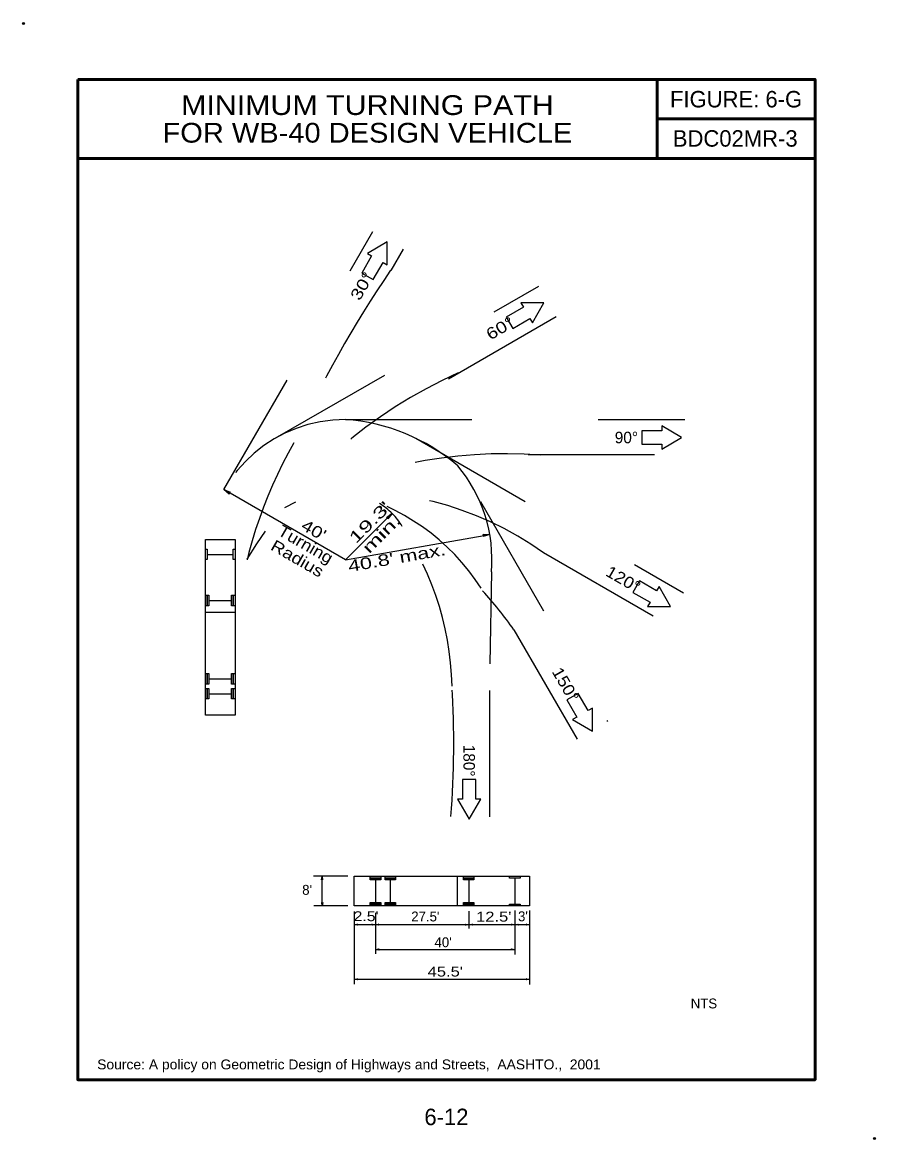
# Model space of a CAD drawing. Extents: x -4.063 to -3.388, y 4.885 to 5.77.
import ezdxf
from ezdxf.enums import TextEntityAlignment as Align

# ---------------------------------------------------------------- set-up
doc = ezdxf.new("R2010")
doc.units = 0
doc.header["$LTSCALE"] = 0.0036
doc.header["$PDMODE"] = 32
doc.header["$PDSIZE"] = 0.0018
doc.linetypes.add('LONG_DASHED', pattern=[7.5, 6, -1.5])
doc.layers.add('1', color=7, linetype='Continuous', lineweight=25)
doc.layers.add('2', color=7, linetype='Continuous', lineweight=25)

msp = doc.modelspace()

# ---------------------------------------------------------------- linework, layer by layer
at = {"layer": '1', "lineweight": 53}
for p, q in [((-3.561125, 5.724317), (-3.561125, 5.661817)), ((-3.561125, 5.693067), (-3.436125, 5.693067)), ((-4.019458, 5.661817), (-3.436125, 5.661817))]:
    msp.add_line(p, q, dxfattribs=at)
at = {"layer": '1', "linetype": 'LONG_DASHED'}
for p, q in [((-3.903883, 5.399658), (-3.785933, 5.60395)), ((-3.771617, 5.573192), (-3.761875, 5.590058)), ((-3.863217, 5.440342), (-3.6548, 5.560675)), ((-3.726175, 5.487367), (-3.640908, 5.536608)), ((-3.807658, 5.455225), (-3.539267, 5.455225)), ((-3.7521, 5.440342), (-3.540125, 5.317967)), ((-3.663042, 5.427442), (-3.539267, 5.427442)), ((-3.700908, 5.390267), (-3.600367, 5.21615)), ((-3.650883, 5.349825), (-3.554008, 5.2939)), ((-3.692167, 5.334567), (-3.693392, 5.261683)), ((-3.674375, 5.288775), (-3.624417, 5.202258))]:
    msp.add_line(p, q, dxfattribs=at)
at = {"layer": '1'}
for p, q in [((-3.903908, 5.399692), (-3.898892, 5.397642)), ((-3.7708, 5.380908), (-3.774058, 5.376592)), ((-3.693458, 5.364233), (-3.6986, 5.362567)), ((-3.917058, 5.348425), (-3.896417, 5.348425)), ((-3.915667, 5.311967), (-3.897808, 5.311967)), ((-3.918458, 5.302733), (-3.895017, 5.302733)), ((-3.915667, 5.2499), (-3.897808, 5.2499)), ((-3.915667, 5.238183), (-3.897808, 5.238183)), ((-3.805925, 5.09365), (-3.833008, 5.09365)), ((-3.826075, 5.070217), (-3.826075, 5.093717)), ((-3.719392, 5.09365), (-3.719392, 5.070217)), ((-3.826133, 5.093533), (-3.825742, 5.090858)), ((-3.78395, 5.090858), (-3.78395, 5.073008)), ((-3.772225, 5.090858), (-3.772225, 5.073008)), ((-3.710167, 5.090858), (-3.710167, 5.073008)), ((-3.673708, 5.092258), (-3.673708, 5.071608)), ((-3.8057, 5.070217), (-3.832792, 5.070217)), ((-3.826092, 5.070283), (-3.826492, 5.072967)), ((-3.800875, 5.065825), (-3.800875, 5.0083)), ((-3.783925, 5.0647), (-3.783925, 5.032267)), ((-3.709992, 5.06605), (-3.709992, 5.052308)), ((-3.673617, 5.066492), (-3.673617, 5.031817)), ((-3.661992, 5.066608), (-3.661992, 5.007983)), ((-3.800875, 5.055408), (-3.661917, 5.055408)), ((-3.800833, 5.055383), (-3.798158, 5.055775)), ((-3.78395, 5.055383), (-3.786625, 5.054983)), ((-3.783942, 5.055408), (-3.781258, 5.0558)), ((-3.710017, 5.05535), (-3.7127, 5.05495)), ((-3.70995, 5.055425), (-3.707267, 5.055817)), ((-3.673617, 5.055408), (-3.676292, 5.055017)), ((-3.6736, 5.055433), (-3.670925, 5.055825)), ((-3.662, 5.055408), (-3.664675, 5.055017)), ((-3.783867, 5.0357), (-3.673783, 5.0357)), ((-3.78385, 5.035733), (-3.781175, 5.036133)), ((-3.673683, 5.035717), (-3.676367, 5.035317)), ((-3.800875, 5.012108), (-3.662042, 5.012108)), ((-3.8008, 5.012117), (-3.798125, 5.012517)), ((-3.662017, 5.012108), (-3.6647, 5.011717))]:
    msp.add_line(p, q, dxfattribs=at)
at = {"layer": '1', "lineweight": 53}
msp.add_lwpolyline([(-4.019458, 5.724317), (-3.436125, 5.724317), (-3.436125, 4.93265), (-4.019458, 4.93265)], close=True, dxfattribs=at)
at = {"layer": '1'}
for points in [[(-3.794767, 5.571117), (-3.78575, 5.565908), (-3.777933, 5.579442), (-3.774558, 5.577483), (-3.77455, 5.595725), (-3.79035, 5.586608), (-3.786958, 5.58465)], [(-3.68045, 5.536267), (-3.675242, 5.527242), (-3.661708, 5.535058), (-3.659758, 5.531675), (-3.650633, 5.547467), (-3.668875, 5.547467), (-3.666917, 5.544075)], [(-3.573092, 5.446142), (-3.573092, 5.435725), (-3.557467, 5.435725), (-3.557467, 5.431817), (-3.541675, 5.440933), (-3.557467, 5.45005), (-3.557467, 5.446142)], [(-3.918458, 5.221258), (-3.918458, 5.360142), (-3.895017, 5.360142), (-3.895017, 5.221258)], [(-3.918458, 5.344258), (-3.918458, 5.352592), (-3.917058, 5.352592), (-3.917058, 5.344258)], [(-3.896417, 5.344258), (-3.896417, 5.352592), (-3.895017, 5.352592), (-3.895017, 5.344258)], [(-3.57505, 5.3274), (-3.580258, 5.318383), (-3.566725, 5.310567), (-3.568683, 5.307192), (-3.55045, 5.307183), (-3.559558, 5.322983), (-3.561517, 5.319592)], [(-3.918458, 5.3078), (-3.918458, 5.316133), (-3.917058, 5.316133), (-3.917058, 5.3078)], [(-3.917058, 5.3078), (-3.917058, 5.316133), (-3.915667, 5.316133), (-3.915667, 5.3078)], [(-3.897808, 5.3078), (-3.897808, 5.316133), (-3.896417, 5.316133), (-3.896417, 5.3078)], [(-3.896417, 5.3078), (-3.896417, 5.316133), (-3.895017, 5.316133), (-3.895017, 5.3078)], [(-3.918458, 5.245733), (-3.918458, 5.254067), (-3.917058, 5.254067), (-3.917058, 5.245733)], [(-3.917058, 5.245733), (-3.917058, 5.254067), (-3.915667, 5.254067), (-3.915667, 5.245733)], [(-3.897808, 5.245733), (-3.897808, 5.254067), (-3.896417, 5.254067), (-3.896417, 5.245733)], [(-3.896417, 5.245733), (-3.896417, 5.254067), (-3.895017, 5.254067), (-3.895017, 5.245733)], [(-3.918458, 5.234017), (-3.918458, 5.24235), (-3.917058, 5.24235), (-3.917058, 5.234017)], [(-3.917058, 5.234017), (-3.917058, 5.24235), (-3.915667, 5.24235), (-3.915667, 5.234017)], [(-3.897808, 5.234017), (-3.897808, 5.24235), (-3.896417, 5.24235), (-3.896417, 5.234017)], [(-3.896417, 5.234017), (-3.896417, 5.24235), (-3.895017, 5.24235), (-3.895017, 5.234017)], [(-3.623433, 5.238383), (-3.632458, 5.233175), (-3.624642, 5.219642), (-3.628033, 5.217692), (-3.612242, 5.208567), (-3.612242, 5.226808), (-3.615625, 5.22485)], [(-3.704592, 5.170217), (-3.715008, 5.170217), (-3.715008, 5.154592), (-3.718917, 5.154592), (-3.7098, 5.1388), (-3.700683, 5.154592), (-3.704592, 5.154592)], [(-3.800875, 5.09365), (-3.661992, 5.09365), (-3.661992, 5.070217), (-3.800875, 5.070217)], [(-3.788117, 5.09365), (-3.779783, 5.09365), (-3.779783, 5.092258), (-3.788117, 5.092258)], [(-3.776392, 5.09365), (-3.768058, 5.09365), (-3.768058, 5.092258), (-3.776392, 5.092258)], [(-3.714333, 5.09365), (-3.706, 5.09365), (-3.706, 5.092258), (-3.714333, 5.092258)], [(-3.677875, 5.09365), (-3.669542, 5.09365), (-3.669542, 5.092258), (-3.677875, 5.092258)], [(-3.788117, 5.092258), (-3.779783, 5.092258), (-3.779783, 5.090858), (-3.788117, 5.090858)], [(-3.776392, 5.092258), (-3.768058, 5.092258), (-3.768058, 5.090858), (-3.776392, 5.090858)], [(-3.714333, 5.092258), (-3.706, 5.092258), (-3.706, 5.090858), (-3.714333, 5.090858)], [(-3.788117, 5.073008), (-3.779783, 5.073008), (-3.779783, 5.071608), (-3.788117, 5.071608)], [(-3.788117, 5.071608), (-3.779783, 5.071608), (-3.779783, 5.070217), (-3.788117, 5.070217)], [(-3.776392, 5.073008), (-3.768058, 5.073008), (-3.768058, 5.071608), (-3.776392, 5.071608)], [(-3.776392, 5.071608), (-3.768058, 5.071608), (-3.768058, 5.070217), (-3.776392, 5.070217)], [(-3.714333, 5.073008), (-3.706, 5.073008), (-3.706, 5.071608), (-3.714333, 5.071608)], [(-3.714333, 5.071608), (-3.706, 5.071608), (-3.706, 5.070217), (-3.714333, 5.070217)], [(-3.677875, 5.071608), (-3.669542, 5.071608), (-3.669542, 5.070217), (-3.677875, 5.070217)]]:
    msp.add_lwpolyline(points, close=True, dxfattribs=at)
for points in [[(-3.900075, 5.397433), (-3.899625, 5.396158), (-3.903958, 5.399733)], [(-3.898892, 5.397617), (-3.900058, 5.39745), (-3.900075, 5.397433)], [(-3.773967, 5.377783), (-3.775308, 5.377675), (-3.77075, 5.380942)], [(-3.774083, 5.3766), (-3.77395, 5.377767), (-3.773967, 5.377783)], [(-3.697842, 5.363492), (-3.699008, 5.364175), (-3.693392, 5.364233)], [(-3.698625, 5.362592), (-3.697842, 5.363475), (-3.697842, 5.363492)], [(-3.826125, 5.091308), (-3.826558, 5.090783), (-3.826125, 5.093567)], [(-3.82575, 5.09085), (-3.826117, 5.091308), (-3.826125, 5.091308)], [(-3.826475, 5.072975), (-3.8261, 5.072517), (-3.826092, 5.072517)], [(-3.826092, 5.072517), (-3.825667, 5.073033), (-3.826092, 5.070258)], [(-3.7986, 5.055383), (-3.798083, 5.05495), (-3.800867, 5.055383)], [(-3.798142, 5.055767), (-3.7986, 5.055392), (-3.7986, 5.055383)], [(-3.786175, 5.055383), (-3.7867, 5.055808), (-3.783917, 5.055383)], [(-3.786633, 5.054992), (-3.786175, 5.055367), (-3.786175, 5.055383)], [(-3.781708, 5.055408), (-3.781192, 5.054975), (-3.783967, 5.055408)], [(-3.78125, 5.055792), (-3.781708, 5.055417), (-3.781708, 5.055408)], [(-3.71225, 5.05535), (-3.712767, 5.055775), (-3.709992, 5.05535)], [(-3.712708, 5.054967), (-3.71225, 5.055342), (-3.71225, 5.05535)], [(-3.707717, 5.055425), (-3.7072, 5.054992), (-3.709975, 5.055425)], [(-3.707258, 5.055808), (-3.707717, 5.055433), (-3.707717, 5.055425)], [(-3.675842, 5.055408), (-3.676367, 5.055842), (-3.673583, 5.055408)], [(-3.6763, 5.055025), (-3.675842, 5.0554), (-3.675842, 5.055408)], [(-3.671375, 5.055433), (-3.67085, 5.055008), (-3.673633, 5.055433)], [(-3.670917, 5.055817), (-3.671375, 5.055442), (-3.671375, 5.055433)], [(-3.664225, 5.055408), (-3.66475, 5.055842), (-3.661967, 5.055408)], [(-3.664683, 5.055025), (-3.664225, 5.0554), (-3.664225, 5.055408)], [(-3.781625, 5.035733), (-3.7811, 5.035308), (-3.783883, 5.035733)], [(-3.781167, 5.036117), (-3.781625, 5.035742), (-3.781625, 5.035733)], [(-3.675917, 5.035717), (-3.676433, 5.036142), (-3.673658, 5.035717)], [(-3.676375, 5.035325), (-3.675917, 5.0357), (-3.675917, 5.035717)], [(-3.798575, 5.012117), (-3.79805, 5.011692), (-3.800833, 5.012117)], [(-3.798117, 5.012508), (-3.798575, 5.012133), (-3.798575, 5.012117)], [(-3.66425, 5.012108), (-3.664767, 5.012533), (-3.661992, 5.012108)], [(-3.664708, 5.011725), (-3.66425, 5.0121), (-3.66425, 5.012108)]]:
    msp.add_lwpolyline(points, dxfattribs=at)
at = {"layer": '1', "linetype": 'LONG_DASHED'}
for centre, radius, start, end in [((-3.012893, 5.058263), 0.917366, 145.83533, 155.63912), ((-3.568649, 5.153366), 0.370246, 113.85469, 148.874), ((-3.807664, 5.344118), 0.111105, 89.99497, 170.96592), ((-3.81896, 5.301927), 0.153712, 49.37802, 85.78193), ((-3.531546, 5.256227), 0.364784, 150.3546, 173.95213), ((-3.680661, 5.047732), 0.380347, 85.84013, 117.44756), ((-3.807654, 5.344108), 0.115886, 355.27621, 40.00076), ((-3.799655, 5.143885), 0.253824, 54.12052, 97.92319), ((-3.847308, 5.227444), 0.17458, 32.6258, 77.03502), ((-3.807654, 5.344108), 0.05209, 30.56823, 58.90801), ((-3.961543, 5.238474), 0.23828, 1.37738, 36.46989), ((-3.952956, 5.091088), 0.341597, 35.36019, 42.00845), ((-4.496259, 5.199129), 0.77424, 355.69143, 3.33738)]:
    msp.add_arc(centre, radius, start, end, dxfattribs=at)
at = {"layer": '1'}
for p in [(-4.062425, 5.768608), (-3.389092, 4.886108)]:
    msp.add_point(p, dxfattribs=at)
at = {"layer": '2'}
for q in [(-3.903883, 5.399658), (-3.770825, 5.380942), (-3.693533, 5.364233)]:
    msp.add_line((-3.807658, 5.344108), q, dxfattribs=at)
at = {"layer": '2', "linetype": 'LONG_DASHED'}
msp.add_line((-3.693392, 5.140642), (-3.693392, 5.261683), dxfattribs=at)

# ---------------------------------------------------------------- texts
at = {"layer": '1'}
for s, height, p in [('FIGURE: 6-G', 0.01303, (-3.498625, 5.702175)), ('BDC02MR-3', 0.01303, (-3.499296, 5.671117)), ("8'", 0.007817, (-3.838004, 5.079008)), ("27.5'", 0.007817, (-3.744463, 5.057933)), ("3'", 0.007817, (-3.667246, 5.058092)), ("40'", 0.007817, (-3.730425, 5.037533)), ('NTS', 0.007817, (-3.524054, 4.989075)), ('6-12', 0.01303, (-3.727792, 4.8967))]:
    msp.add_text(s, height=height, dxfattribs=at).set_placement(p, align=Align.CENTER)
for s, height, width, p in [('MINIMUM TURNING PATH', 0.01562, 1.15, (-3.790292, 5.696192)), ('FOR WB-40 DESIGN VEHICLE', 0.01562, 1.1, (-3.790292, 5.674317)), ("2.5'", 0.007817, 1.2, (-3.791367, 5.058142)), ("12.5'", 0.007817, 1.25, (-3.690346, 5.057783)), ("45.5'", 0.007817, 1.25, (-3.728671, 5.014325))]:
    msp.add_text(s, height=height, dxfattribs=dict(at, width=width)).set_placement(p, align=Align.CENTER)
for s, rotation, width, p in [('30°', 60, 1.25, (-3.784971, 5.568546)), ('60°', 30, 1.25, (-3.673121, 5.529224)), ('120°', 330, 1.15, (-3.577596, 5.317597)), ('150°', 300, 1.15, (-3.630247, 5.230654))]:
    msp.add_text(s, height=0.009108, rotation=rotation, dxfattribs=dict(at, width=width)).set_placement(p, align=Align.RIGHT)
msp.add_text('90°', height=0.009108, dxfattribs=at).set_placement((-3.5762, 5.436375), align=Align.RIGHT)
for s, rotation, width, p in [("19.3'", 45, 1.55, (-3.785177, 5.370606)), ('Turning', 330.003, 1.15, (-3.841471, 5.352483)), ("40'", 330.003, 1.25, (-3.834966, 5.363772)), ('min.', 45, 1.6, (-3.775973, 5.361402)), ('Radius', 330.003, 1.2, (-3.847979, 5.341213)), ("40.8' max.", 10.001, 1.4, (-3.766233, 5.341209))]:
    msp.add_text(s, height=0.009117, rotation=rotation, dxfattribs=dict(at, width=width)).set_placement(p, align=Align.CENTER)
msp.add_text('180°', height=0.009108, rotation=270, dxfattribs=at).set_placement((-3.714358, 5.172592), align=Align.RIGHT)
at = {"layer": '1', "width": 1.05}
msp.add_text('Source: A policy on Geometric Design of Highways and Streets,  AASHTO.,  2001', height=0.007817, dxfattribs=at).set_placement((-4.004125, 4.940842))

doc.saveas('drawing.dxf')
